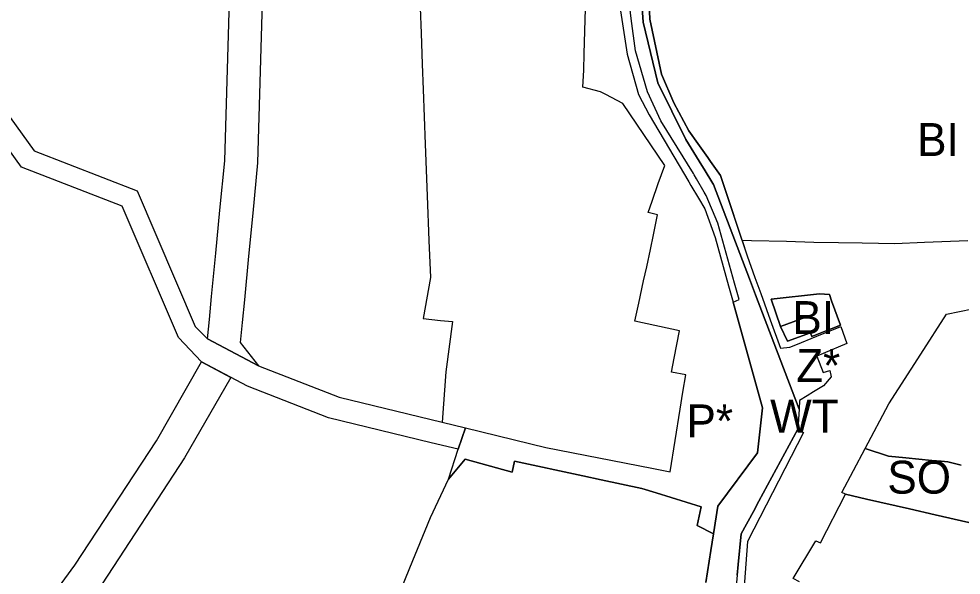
# Model space of a CAD drawing. Extents: x -521621 to -516769, y -1190068 to -1185078.
# Drawn here: x -519076.4 to -518790.4, y -1186922.3 to -1186753.4 of the extents above; entities that cross this region are included whole.
import ezdxf

# ---------------------------------------------------------------- set-up
doc = ezdxf.new("R2010")
doc.units = 0
for name, color, linetype in [('bydleni_s', 7, 'Continuous'), ('s_zelen_s', 7, 'Continuous'), ('sm_vyuziti_s', 7, 'Continuous'), ('v_infrastr_n', 7, 'Continuous'), ('v_infrastr_s', 7, 'Continuous'), ('voda_s', 7, 'Continuous')]:
    doc.layers.add(name, color=color, linetype=linetype)

msp = doc.modelspace()

# ---------------------------------------------------------------- linework, layer by layer
at = {"layer": 'bydleni_s'}
for p, q in [((-518904.91, -1186763.85), (-518904.18, -1186739.87)), ((-518954.01, -1186767.14), (-518953.71, -1186774.81)), ((-518953.71, -1186774.81), (-518953.08, -1186791.41)), ((-518953.08, -1186791.41), (-518952.48, -1186807.06)), ((-518835.13, -1186821.24), (-518843.43, -1186821.02)), ((-518810.54, -1186821.66), (-518820.51, -1186821.49)), ((-518801.54, -1186821.32), (-518810.54, -1186821.66)), ((-518788.4, -1186820.82), (-518801.54, -1186821.32)), ((-518812.4, -1186870.24), (-518802.69, -1186855.15)), ((-518819.61, -1186883.87), (-518812.4, -1186870.24)), ((-518833.13, -1186912.44), (-518825.58, -1186897.69)), ((-518866.42, -1186914.8), (-518867.97, -1186924.47))]:
    msp.add_line(p, q, dxfattribs=at)
for points in [[(-518955.84, -1186719.13), (-518954.36, -1186757.76), (-518954.01, -1186767.14)], [(-518884.9, -1186753.45), (-518885.91, -1186729.7)], [(-518867.35, -1186795.52), (-518870.41, -1186791.2), (-518873.11, -1186787.39), (-518877.66, -1186778.88), (-518881.36, -1186770.21), (-518884.9, -1186753.45)], [(-518905.22, -1186774.09), (-518905.01, -1186769), (-518904.91, -1186763.85)], [(-518893.12, -1186779.08), (-518898.33, -1186776.39), (-518899.91, -1186775.58), (-518905.22, -1186774.09)], [(-518882.4, -1186803.38), (-518880.36, -1186797.87), (-518893.12, -1186779.08)], [(-518843.43, -1186821.02), (-518854.08, -1186820.74), (-518856.96, -1186820.66), (-518863.51, -1186800.95), (-518866.52, -1186796.7), (-518867.35, -1186795.52)], [(-518885.48, -1186812.19), (-518884.26, -1186808.71), (-518882.4, -1186803.38)], [(-518952.48, -1186807.06), (-518951.96, -1186820.67), (-518951.96, -1186820.67), (-518951.53, -1186831.9)], [(-518884.74, -1186823.44), (-518883.83, -1186818.91), (-518882.61, -1186812.83), (-518885.48, -1186812.19)], [(-518820.51, -1186821.49), (-518827.7, -1186821.37), (-518835.13, -1186821.24)], [(-518886.82, -1186832.93), (-518885.89, -1186828.67), (-518884.74, -1186823.44)], [(-518951.53, -1186831.9), (-518951.53, -1186831.9), (-518953.69, -1186844.37), (-518948.45, -1186844.93), (-518944.8, -1186845.31)], [(-518889.51, -1186845.19), (-518888.31, -1186839.7), (-518886.82, -1186832.93)], [(-518833.45, -1186836.9), (-518848.14, -1186838.51)], [(-518848.14, -1186838.51), (-518845.32, -1186846.76)], [(-518829.83, -1186839.01), (-518830.38, -1186837.04), (-518833.45, -1186836.9)], [(-518832.19, -1186848.44), (-518827.11, -1186846.35), (-518829.83, -1186839.01)], [(-518802.69, -1186855.15), (-518794.9, -1186843.06), (-518783.09, -1186840.61), (-518780.65, -1186840.1), (-518771.03, -1186842.13), (-518761.45, -1186844.15)], [(-518834.88, -1186842.97), (-518845.32, -1186846.76)], [(-518845.32, -1186846.76), (-518837.56, -1186843.94)], [(-518837.56, -1186843.94), (-518834.88, -1186842.97)], [(-518944.8, -1186845.31), (-518946.82, -1186860.58), (-518948, -1186875.83)], [(-518878.37, -1186860.69), (-518877.54, -1186856.4), (-518875.93, -1186848.06), (-518889.51, -1186845.19)], [(-518845.32, -1186846.76), (-518843.17, -1186851.28), (-518836.19, -1186848.68)], [(-518836.19, -1186848.68), (-518835.78, -1186849.79)], [(-518835.78, -1186849.79), (-518832.19, -1186848.44)], [(-518875.71, -1186871.87), (-518874.87, -1186866.68), (-518874.02, -1186861.43), (-518878.37, -1186860.69)], [(-518948, -1186875.83), (-518940.88, -1186877.56), (-518916.47, -1186883.51), (-518916.47, -1186883.51), (-518884.36, -1186889.83), (-518878.79, -1186890.93), (-518875.71, -1186871.87)], [(-518812.45, -1186886.19), (-518819.61, -1186883.87)], [(-518946.08, -1186893.11), (-518940.94, -1186887.07), (-518926.7, -1186891.04)], [(-518926.7, -1186891.04), (-518926, -1186887.69), (-518905.22, -1186892.12), (-518899.68, -1186893.3), (-518887.35, -1186895.93)], [(-518807.19, -1186886.69), (-518812.45, -1186886.19)], [(-518799.32, -1186887.44), (-518807.19, -1186886.69)], [(-518796.54, -1186887.7), (-518799.32, -1186887.44)], [(-518794.54, -1186887.89), (-518796.54, -1186887.7)], [(-518790.45, -1186888.88), (-518794.54, -1186887.89)], [(-518957.73, -1186920.08), (-518957.73, -1186920.08), (-518951.47, -1186904.79), (-518946.08, -1186893.11)], [(-518887.35, -1186895.93), (-518882.99, -1186897.3), (-518869.35, -1186901.58), (-518870.6, -1186907.23), (-518865.61, -1186909.77), (-518866.42, -1186914.8)], [(-518825.58, -1186897.69), (-518819.17, -1186899.16)], [(-518819.17, -1186899.16), (-518806.14, -1186902.14)], [(-518806.14, -1186902.14), (-518798.31, -1186903.93)], [(-518798.31, -1186903.93), (-518725.89, -1186920.49)], [(-518839.49, -1186924.32), (-518841.43, -1186923.31), (-518834.52, -1186911.88), (-518833.13, -1186912.44)], [(-518997.19, -1187016.52), (-518989.35, -1186997.36), (-518984.03, -1186984.36), (-518978.68, -1186971.28), (-518966.28, -1186940.98), (-518957.73, -1186920.08)]]:
    msp.add_lwpolyline(points, dxfattribs=at)
at = {"layer": 's_zelen_s'}
for points in [[(-518843.2, -1186567.12), (-518847.91, -1186577.13), (-518859.8, -1186598.03), (-518877.19, -1186628.77), (-518880.09, -1186633.48), (-518884.33, -1186640.2), (-518888.24, -1186649.02), (-518894.07, -1186660.97), (-518896.76, -1186673.37), (-518899.27, -1186684.95), (-518897.26, -1186718.8), (-518894.82, -1186744.27), (-518891.85, -1186764.12), (-518888.34, -1186776.32), (-518885.16, -1186782.48), (-518873.11, -1186802.87), (-518872.45, -1186803.99), (-518870.19, -1186807.8), (-518868.29, -1186811.02), (-518865.1, -1186819.73), (-518861.03, -1186834.46)], [(-518859.27, -1186833.63), (-518864.25, -1186815.37), (-518867.86, -1186806.99), (-518868.43, -1186805.99), (-518870.76, -1186801.91), (-518871.43, -1186800.73), (-518871.68, -1186800.3), (-518881.62, -1186784.32), (-518885.69, -1186775.58), (-518889.3, -1186763.06), (-518890.57, -1186753.29), (-518894.18, -1186722.73), (-518897.05, -1186684.52), (-518894.83, -1186674.94), (-518892.06, -1186662.98), (-518882.83, -1186642.18), (-518882.39, -1186641.41), (-518846.74, -1186579.46), (-518842.49, -1186569.14)], [(-518839.51, -1186869.24), (-518839.66, -1186871.85), (-518852.85, -1186837.2), (-518854.7, -1186832.35), (-518865.62, -1186803.68), (-518865.83, -1186803.33), (-518868.44, -1186799.06), (-518869.18, -1186797.85), (-518873.98, -1186790), (-518882.54, -1186772.81), (-518886.92, -1186754.41), (-518889.95, -1186711.48)], [(-518885.91, -1186729.7), (-518884.9, -1186753.45), (-518881.36, -1186770.21), (-518877.66, -1186778.88), (-518873.11, -1186787.39), (-518870.41, -1186791.2), (-518867.35, -1186795.52), (-518866.52, -1186796.7), (-518863.51, -1186800.95), (-518855.43, -1186825.28), (-518853.04, -1186831.89), (-518851.28, -1186836.75), (-518848.38, -1186844.75), (-518845.25, -1186853.38)], [(-518861.03, -1186834.46), (-518859.67, -1186839.37), (-518857.78, -1186838.62), (-518859.27, -1186833.63)], [(-518834.29, -1186849.75), (-518826.96, -1186846.76), (-518825.11, -1186851.98), (-518832.37, -1186855)], [(-518845.25, -1186853.38), (-518842.46, -1186853.07), (-518840.62, -1186852.32), (-518834.29, -1186849.75)], [(-518832.37, -1186855), (-518834.21, -1186855.77), (-518832.35, -1186860.74), (-518830.33, -1186860.15), (-518829.86, -1186862.05), (-518832.27, -1186864.78), (-518835.27, -1186866.63), (-518837.15, -1186867.79), (-518839.51, -1186869.24)], [(-518838.25, -1186879.01), (-518855.26, -1186912.05)], [(-518851.82, -1186899.83), (-518840.02, -1186878)], [(-518840.02, -1186878), (-518838.25, -1186879.01)], [(-518853.52, -1186902.98), (-518851.82, -1186899.83)], [(-518857.19, -1186909.77), (-518853.52, -1186902.98)], [(-518858.08, -1186919.06), (-518857.19, -1186909.77)], [(-518855.26, -1186912.05), (-518856.49, -1186928.34)], [(-518858.39, -1186922.28), (-518858.08, -1186919.06)]]:
    msp.add_lwpolyline(points, dxfattribs=at)
at = {"layer": 'sm_vyuziti_s'}
for points in [[(-518798.31, -1186903.93), (-518806.14, -1186902.14), (-518819.17, -1186899.16), (-518825.58, -1186897.69), (-518826.68, -1186897.23), (-518819.61, -1186883.87), (-518812.45, -1186886.19), (-518807.19, -1186886.69), (-518799.32, -1186887.44), (-518796.54, -1186887.7), (-518794.54, -1186887.89), (-518790.45, -1186888.88)], [(-518725.89, -1186920.49), (-518798.31, -1186903.93)]]:
    msp.add_lwpolyline(points, dxfattribs=at)
at = {"layer": 'v_infrastr_n'}
msp.add_line((-518940.88, -1186877.56), (-518943.06, -1186884.07), dxfattribs=at)
for points in [[(-519000.63, -1186681.98), (-519003.96, -1186797.13), (-519005.44, -1186812.42), (-519006.7, -1186825.45), (-519007.97, -1186838.64), (-519008.64, -1186845.57), (-519009.23, -1186851.67), (-519003.75, -1186858.69), (-519019.17, -1186850.57), (-519018.59, -1186844.61), (-519017.92, -1186837.68), (-519016.65, -1186824.49), (-519015.39, -1186811.46), (-519013.95, -1186796.5), (-519010.62, -1186681.73)], [(-519090.1, -1186768.1), (-519071.8, -1186793.45), (-519040.52, -1186805.58), (-519022.9, -1186846.8), (-519019.17, -1186850.57), (-519003.75, -1186858.69)], [(-519007.04, -1186864.93), (-519020.96, -1186857.56), (-519027.99, -1186850.15), (-519045.05, -1186810.26), (-519075.63, -1186798.4), (-519095.14, -1186771.38)], [(-519085.78, -1186947.47), (-519075.41, -1186941.15), (-519059.42, -1186919.2), (-519034.68, -1186881.46), (-519020.96, -1186857.56), (-519012.12, -1186862.24), (-519026.15, -1186886.69), (-519051.19, -1186924.89), (-519068.5, -1186948.65), (-519087.09, -1186959.97)], [(-519003.75, -1186858.69), (-518979.19, -1186868.23), (-518948, -1186875.83)], [(-518943.06, -1186884.07), (-518951.29, -1186882.07), (-518982.48, -1186874.47), (-519007.04, -1186864.93)], [(-518948, -1186875.83), (-518940.88, -1186877.56)]]:
    msp.add_lwpolyline(points, dxfattribs=at)
at = {"layer": 'v_infrastr_s'}
for p, q in [((-518943.06, -1186884.07), (-518940.88, -1186877.56)), ((-518946.08, -1186893.11), (-518943.06, -1186884.07))]:
    msp.add_line(p, q, dxfattribs=at)
for points in [[(-518940.88, -1186877.56), (-518916.47, -1186883.51), (-518884.36, -1186889.83), (-518878.79, -1186890.93), (-518875.71, -1186871.87), (-518874.87, -1186866.68), (-518874.02, -1186861.43), (-518878.37, -1186860.69), (-518877.54, -1186856.4), (-518875.93, -1186848.06), (-518889.51, -1186845.19), (-518888.31, -1186839.7), (-518886.82, -1186832.93), (-518885.89, -1186828.67), (-518884.74, -1186823.44), (-518883.83, -1186818.91), (-518882.61, -1186812.83), (-518885.48, -1186812.19), (-518884.26, -1186808.71), (-518882.4, -1186803.38), (-518880.36, -1186797.87), (-518893.12, -1186779.08), (-518898.33, -1186776.39), (-518899.91, -1186775.58), (-518905.22, -1186774.09), (-518905.01, -1186769), (-518904.91, -1186763.85), (-518904.18, -1186739.87)], [(-518894.82, -1186744.27), (-518891.85, -1186764.12), (-518888.34, -1186776.32), (-518885.16, -1186782.48), (-518873.11, -1186802.87), (-518872.45, -1186803.99), (-518870.19, -1186807.8), (-518868.29, -1186811.02), (-518865.1, -1186819.73), (-518861.03, -1186834.46), (-518859.67, -1186839.37), (-518850.78, -1186871.51), (-518852.26, -1186885.1), (-518864.25, -1186901.33), (-518865.61, -1186909.77), (-518870.6, -1186907.23), (-518869.35, -1186901.58), (-518882.99, -1186897.3), (-518887.35, -1186895.93), (-518899.68, -1186893.3), (-518905.22, -1186892.12), (-518926, -1186887.69), (-518926.7, -1186891.04), (-518940.94, -1186887.07)], [(-518788.4, -1186820.82), (-518801.54, -1186821.32), (-518810.54, -1186821.66), (-518820.51, -1186821.49), (-518827.7, -1186821.37), (-518835.13, -1186821.24), (-518843.43, -1186821.02), (-518854.08, -1186820.74), (-518856.96, -1186820.66), (-518855.43, -1186825.28), (-518853.04, -1186831.89), (-518851.28, -1186836.75), (-518848.38, -1186844.75), (-518845.25, -1186853.38), (-518842.46, -1186853.07), (-518840.62, -1186852.32), (-518834.29, -1186849.75), (-518826.96, -1186846.76), (-518825.11, -1186851.98), (-518832.37, -1186855), (-518834.21, -1186855.77), (-518832.35, -1186860.74), (-518830.33, -1186860.15), (-518829.86, -1186862.05)], [(-518848.14, -1186838.51), (-518833.45, -1186836.9)], [(-518845.32, -1186846.76), (-518848.14, -1186838.51)], [(-518833.45, -1186836.9), (-518830.38, -1186837.04), (-518829.83, -1186839.01)], [(-518829.83, -1186839.01), (-518827.11, -1186846.35)], [(-518841.43, -1186923.31), (-518834.52, -1186911.88), (-518833.13, -1186912.44), (-518825.58, -1186897.69), (-518826.68, -1186897.23), (-518819.61, -1186883.87), (-518812.4, -1186870.24), (-518802.69, -1186855.15), (-518794.9, -1186843.06), (-518783.09, -1186840.61)], [(-518845.32, -1186846.76), (-518834.88, -1186842.97)], [(-518837.56, -1186843.94), (-518845.32, -1186846.76)], [(-518834.88, -1186842.97), (-518837.56, -1186843.94)], [(-518843.17, -1186851.28), (-518845.32, -1186846.76)], [(-518827.11, -1186846.35), (-518832.19, -1186848.44)], [(-518836.19, -1186848.68), (-518843.17, -1186851.28)], [(-518835.78, -1186849.79), (-518836.19, -1186848.68)], [(-518832.19, -1186848.44), (-518835.78, -1186849.79)], [(-518829.86, -1186862.05), (-518832.27, -1186864.78), (-518835.27, -1186866.63), (-518837.15, -1186867.79), (-518839.51, -1186869.24), (-518839.66, -1186871.85), (-518840.02, -1186878), (-518838.25, -1186879.01)], [(-518838.25, -1186879.01), (-518855.26, -1186912.05), (-518856.49, -1186928.34), (-518865.87, -1186975.23), (-518876.39, -1187016.44), (-518882.26, -1187031.41), (-518890.88, -1187044.67), (-518899.59, -1187054.9), (-518901.68, -1187074.51), (-518905.37, -1187082.65)], [(-518940.94, -1186887.07), (-518946.08, -1186893.11)]]:
    msp.add_lwpolyline(points, dxfattribs=at)
at = {"layer": 'voda_s'}
for points in [[(-518889.95, -1186711.48), (-518886.92, -1186754.41)], [(-518889.3, -1186763.06), (-518890.57, -1186753.29)], [(-518886.92, -1186754.41), (-518882.54, -1186772.81)], [(-518885.69, -1186775.58), (-518889.3, -1186763.06)], [(-518882.54, -1186772.81), (-518873.98, -1186790)], [(-518881.62, -1186784.32), (-518885.69, -1186775.58)], [(-518871.68, -1186800.3), (-518881.62, -1186784.32)], [(-518873.98, -1186790), (-518869.18, -1186797.85)], [(-518869.18, -1186797.85), (-518868.44, -1186799.06)], [(-518868.44, -1186799.06), (-518865.83, -1186803.33)], [(-518871.43, -1186800.73), (-518871.68, -1186800.3)], [(-518870.76, -1186801.91), (-518871.43, -1186800.73)], [(-518868.43, -1186805.99), (-518870.76, -1186801.91)], [(-518865.83, -1186803.33), (-518865.62, -1186803.68)], [(-518865.62, -1186803.68), (-518854.7, -1186832.35)], [(-518867.86, -1186806.99), (-518868.43, -1186805.99)], [(-518864.25, -1186815.37), (-518867.86, -1186806.99)], [(-518859.27, -1186833.63), (-518864.25, -1186815.37)], [(-518857.78, -1186838.62), (-518859.27, -1186833.63)], [(-518854.7, -1186832.35), (-518852.85, -1186837.2)], [(-518867.97, -1186924.47), (-518866.42, -1186914.8), (-518865.61, -1186909.77), (-518864.25, -1186901.33), (-518852.26, -1186885.1), (-518850.78, -1186871.51), (-518859.67, -1186839.37), (-518857.78, -1186838.62)], [(-518852.85, -1186837.2), (-518839.66, -1186871.85)], [(-518839.66, -1186871.85), (-518840.02, -1186878)], [(-518840.02, -1186878), (-518851.82, -1186899.83)], [(-518851.82, -1186899.83), (-518853.52, -1186902.98)], [(-518853.52, -1186902.98), (-518857.19, -1186909.77)], [(-518857.19, -1186909.77), (-518858.08, -1186919.06)], [(-518858.08, -1186919.06), (-518858.39, -1186922.28)], [(-518858.39, -1186922.28), (-518859.24, -1186931.12)]]:
    msp.add_lwpolyline(points, dxfattribs=at)

# ---------------------------------------------------------------- texts
at = {"layer": 'bydleni_s'}
for p in [(-518803.8, -1186795.02), (-518841.66, -1186849.08)]:
    msp.add_text('BI', height=10, dxfattribs=at).set_placement(p)
at = {"layer": 's_zelen_s'}
msp.add_text('Z*', height=10, dxfattribs=at).set_placement((-518840.51, -1186863.61))
at = {"layer": 'sm_vyuziti_s'}
msp.add_text('SO', height=10, dxfattribs=at).set_placement((-518812.85, -1186897.53))
at = {"layer": 'v_infrastr_s'}
msp.add_text('P*', height=10, dxfattribs=at).set_placement((-518873.8, -1186880.45))
at = {"layer": 'voda_s'}
msp.add_text('WT', height=10, dxfattribs=at).set_placement((-518848.42, -1186879.01))

doc.saveas('drawing.dxf')
